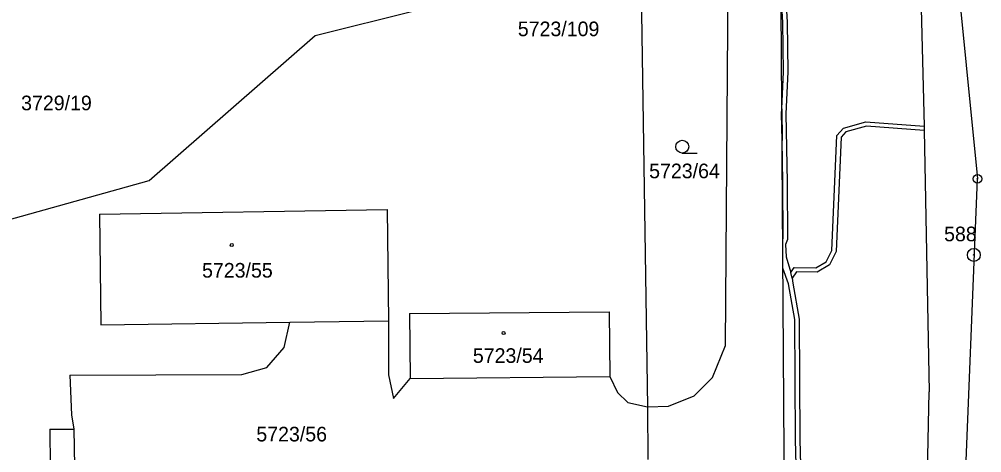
# Model space of a CAD drawing. Extents: x -735092 to -733385, y -1122435 to -1118992.
# Drawn here: x -734488.5 to -734376.6, y -1120662.2 to -1120611.8 of the extents above; entities that cross this region are included whole.
import ezdxf

# ---------------------------------------------------------------- set-up
doc = ezdxf.new("R2010")
doc.units = 0
for name, color, linetype in [('Vrstva 1', 7, 'Continuous'), ('Vrstva 16', 7, 'Continuous'), ('Vrstva 17', 7, 'Continuous'), ('Vrstva 18', 7, 'Continuous'), ('Vrstva 19', 7, 'Continuous'), ('Vrstva 25', 7, 'Continuous'), ('Vrstva 27', 7, 'Continuous')]:
    doc.layers.add(name, color=color, linetype=linetype)

msp = doc.modelspace()

# ---------------------------------------------------------------- linework, layer by layer
at = {"layer": 'Vrstva 1'}
for points in [[(-734398.51, -1120823.51), (-734400.41, -1120541.08)], [(-734384.22, -1120589.2), (-734383.34, -1120624.21), (-734383.33, -1120624.71), (-734383.28, -1120626.68)], [(-734381.06, -1120590.62), (-734377.13, -1120630.33)], [(-734406.43, -1120649.74), (-734406.05, -1120602.2)], [(-734454.12, -1120613.68), (-734430.46, -1120607.72)], [(-734416.2, -1120608.46), (-734415.5, -1120656.88)], [(-734473.4, -1120630.53), (-734454.12, -1120613.68)], [(-734383.28, -1120626.68), (-734382.74, -1120655.13)], [(-734503.83, -1120639.03), (-734473.4, -1120630.53)], [(-734378.7, -1120669.89), (-734377.13, -1120630.33)], [(-734479.19, -1120634.45), (-734445.76, -1120633.91)], [(-734445.76, -1120633.91), (-734445.58, -1120646.87)], [(-734479.19, -1120634.45), (-734479.03, -1120647.34)], [(-734443.13, -1120645.99), (-734419.93, -1120645.81)], [(-734443.13, -1120645.99), (-734443.05, -1120653.57)], [(-734419.93, -1120645.81), (-734419.85, -1120653.32)], [(-734479.03, -1120647.34), (-734457.04, -1120647.03)], [(-734457.7, -1120649.98), (-734457.04, -1120647.03)], [(-734457.04, -1120647.03), (-734445.58, -1120646.87)], [(-734445.58, -1120646.87), (-734445.57, -1120653.15)], [(-734459.71, -1120652.27), (-734457.7, -1120649.98)], [(-734407.91, -1120653.46), (-734406.43, -1120649.74)], [(-734482.61, -1120653.2), (-734462.65, -1120653.1)], [(-734482.61, -1120653.2), (-734482.44, -1120657.79)], [(-734462.65, -1120653.1), (-734459.71, -1120652.27)], [(-734445.57, -1120653.15), (-734444.99, -1120655.9)], [(-734443.05, -1120653.57), (-734419.85, -1120653.32)], [(-734419.85, -1120653.32), (-734418.98, -1120655.18)], [(-734444.99, -1120655.9), (-734443.05, -1120653.57)], [(-734410.07, -1120655.57), (-734407.91, -1120653.46)], [(-734418.98, -1120655.18), (-734417.76, -1120656.35)], [(-734413.03, -1120656.77), (-734410.07, -1120655.57)], [(-734384.01, -1120717.12), (-734382.74, -1120655.13)], [(-734417.76, -1120656.35), (-734415.5, -1120656.88)], [(-734482.44, -1120657.79), (-734482.15, -1120659.47)], [(-734415.5, -1120656.88), (-734413.03, -1120656.77)], [(-734415.5, -1120656.88), (-734415.43, -1120663)], [(-734484.95, -1120659.46), (-734482.15, -1120659.47)], [(-734484.95, -1120659.46), (-734484.91, -1120663.81)], [(-734482.15, -1120659.47), (-734482.1, -1120663.78)]]:
    msp.add_lwpolyline(points, dxfattribs=at)
at = {"layer": 'Vrstva 25'}
msp.add_lwpolyline([(-734411.44, -1120627.35), (-734409.69, -1120627.35)], dxfattribs=at)
for centre, radius in [((-734411.44, -1120626.6), 0.75), ((-734377.13, -1120630.33), 0.5), ((-734377.13, -1120630.33), 0.032), ((-734463.8, -1120638.04), 0.175), ((-734377.55, -1120639.19), 0.75), ((-734377.55, -1120639.19), 0.032), ((-734432.21, -1120648.28), 0.175)]:
    msp.add_circle(centre, radius, dxfattribs=at)
at = {"layer": 'Vrstva 27'}
for points in [[(-734398.13, -1120666.61), (-734398.29, -1120660.68), (-734398.37, -1120646.71), (-734399.09, -1120642.57), (-734399.74, -1120640.75), (-734399.76, -1120637.42), (-734399.7, -1120637.28), (-734399.76, -1120630.72), (-734399.84, -1120625.86), (-734399.89, -1120622.79), (-734399.86, -1120622.21), (-734399.67, -1120617.88), (-734399.76, -1120612.14), (-734399.95, -1120608.85), (-734400.06, -1120593.63), (-734400.05, -1120587.29), (-734399.94, -1120578.43), (-734399.87, -1120572.74), (-734399.8, -1120561.05), (-734400.06, -1120553.66), (-734399.96, -1120545.08), (-734399.77, -1120544.21), (-734395.54, -1120535.39)], [(-734395.06, -1120535.53), (-734399.29, -1120544.37), (-734399.46, -1120545.14), (-734399.56, -1120553.66), (-734399.3, -1120561.05), (-734399.37, -1120572.74), (-734399.44, -1120578.43), (-734399.55, -1120587.29), (-734399.57, -1120606.87), (-734399.26, -1120612.12), (-734399.17, -1120617.88), (-734399.39, -1120622.79), (-734399.26, -1120630.72), (-734399.2, -1120637.38), (-734399.46, -1120637.96), (-734399.36, -1120639.42), (-734398.84, -1120641.24), (-734398.44, -1120640.65), (-734395.91, -1120640.71)], [(-734399.57, -1120606.87), (-734399.26, -1120612.12), (-734399.17, -1120617.88), (-734399.39, -1120622.79), (-734399.26, -1120630.72), (-734399.2, -1120637.38), (-734399.46, -1120637.96), (-734399.36, -1120639.42), (-734398.84, -1120641.24), (-734398.44, -1120640.65), (-734395.91, -1120640.71), (-734394.72, -1120640), (-734394.07, -1120638.67), (-734393.49, -1120625.29), (-734392.69, -1120624.44), (-734390.09, -1120623.7), (-734383.34, -1120624.21), (-734383.33, -1120624.71)], [(-734398.13, -1120666.61), (-734398.29, -1120660.68), (-734398.37, -1120646.71), (-734399.09, -1120642.57), (-734399.74, -1120640.75), (-734399.76, -1120637.42), (-734399.7, -1120637.28), (-734399.76, -1120630.72), (-734399.84, -1120625.86), (-734399.89, -1120622.79), (-734399.86, -1120622.21), (-734399.67, -1120617.88), (-734399.76, -1120612.14), (-734399.95, -1120608.85)], [(-734399.84, -1120625.86), (-734399.89, -1120622.79), (-734399.86, -1120622.21), (-734399.84, -1120625.86)], [(-734383.33, -1120624.71), (-734390.03, -1120624.2), (-734392.42, -1120624.88), (-734392.99, -1120625.49), (-734393.57, -1120638.79), (-734394.34, -1120640.36), (-734395.77, -1120641.21), (-734398.18, -1120641.15), (-734398.67, -1120641.89), (-734398.6, -1120642.46), (-734397.87, -1120646.67), (-734397.79, -1120660.68), (-734397.63, -1120666.6)], [(-734395.91, -1120640.71), (-734394.72, -1120640), (-734394.07, -1120638.67), (-734393.49, -1120625.29), (-734392.69, -1120624.44), (-734390.09, -1120623.7), (-734383.34, -1120624.21), (-734383.33, -1120624.71), (-734390.03, -1120624.2), (-734392.42, -1120624.88), (-734392.99, -1120625.49), (-734393.57, -1120638.79), (-734394.34, -1120640.36), (-734395.77, -1120641.21)], [(-734392.69, -1120624.44), (-734390.09, -1120623.7), (-734383.34, -1120624.21), (-734383.33, -1120624.71)], [(-734383.33, -1120624.71), (-734390.03, -1120624.2), (-734392.42, -1120624.88)], [(-734392.42, -1120624.88), (-734392.99, -1120625.49), (-734393.57, -1120638.79), (-734394.34, -1120640.36)], [(-734394.07, -1120638.67), (-734393.49, -1120625.29), (-734392.69, -1120624.44)], [(-734398.84, -1120641.24), (-734398.44, -1120640.65), (-734395.91, -1120640.71), (-734394.72, -1120640), (-734394.07, -1120638.67)], [(-734394.34, -1120640.36), (-734395.77, -1120641.21), (-734398.18, -1120641.15), (-734398.67, -1120641.89), (-734398.84, -1120641.24)], [(-734395.77, -1120641.21), (-734398.18, -1120641.15), (-734398.67, -1120641.89), (-734398.6, -1120642.46), (-734397.87, -1120646.67), (-734397.79, -1120660.68), (-734397.63, -1120666.6)]]:
    msp.add_lwpolyline(points, dxfattribs=at)

# ---------------------------------------------------------------- texts
at = {"layer": 'Vrstva 16'}
msp.add_text('5723/109', height=1.7, dxfattribs=at).set_placement((-734430.558, -1120613.74))
at = {"layer": 'Vrstva 17'}
msp.add_text('588', height=1.7, dxfattribs=at).set_placement((-734381.01, -1120637.6))
at = {"layer": 'Vrstva 18'}
for s, p in [('3729/19', (-734488.29, -1120622.36)), ('5723/64', (-734415.29, -1120630.27)), ('5723/56', (-734460.95, -1120660.89))]:
    msp.add_text(s, height=1.7, dxfattribs=at).set_placement(p)
at = {"layer": 'Vrstva 19'}
for s, p in [('5723/55', (-734467.26, -1120641.83)), ('5723/54', (-734435.78, -1120651.75))]:
    msp.add_text(s, height=1.7, dxfattribs=at).set_placement(p)

doc.saveas('drawing.dxf')
